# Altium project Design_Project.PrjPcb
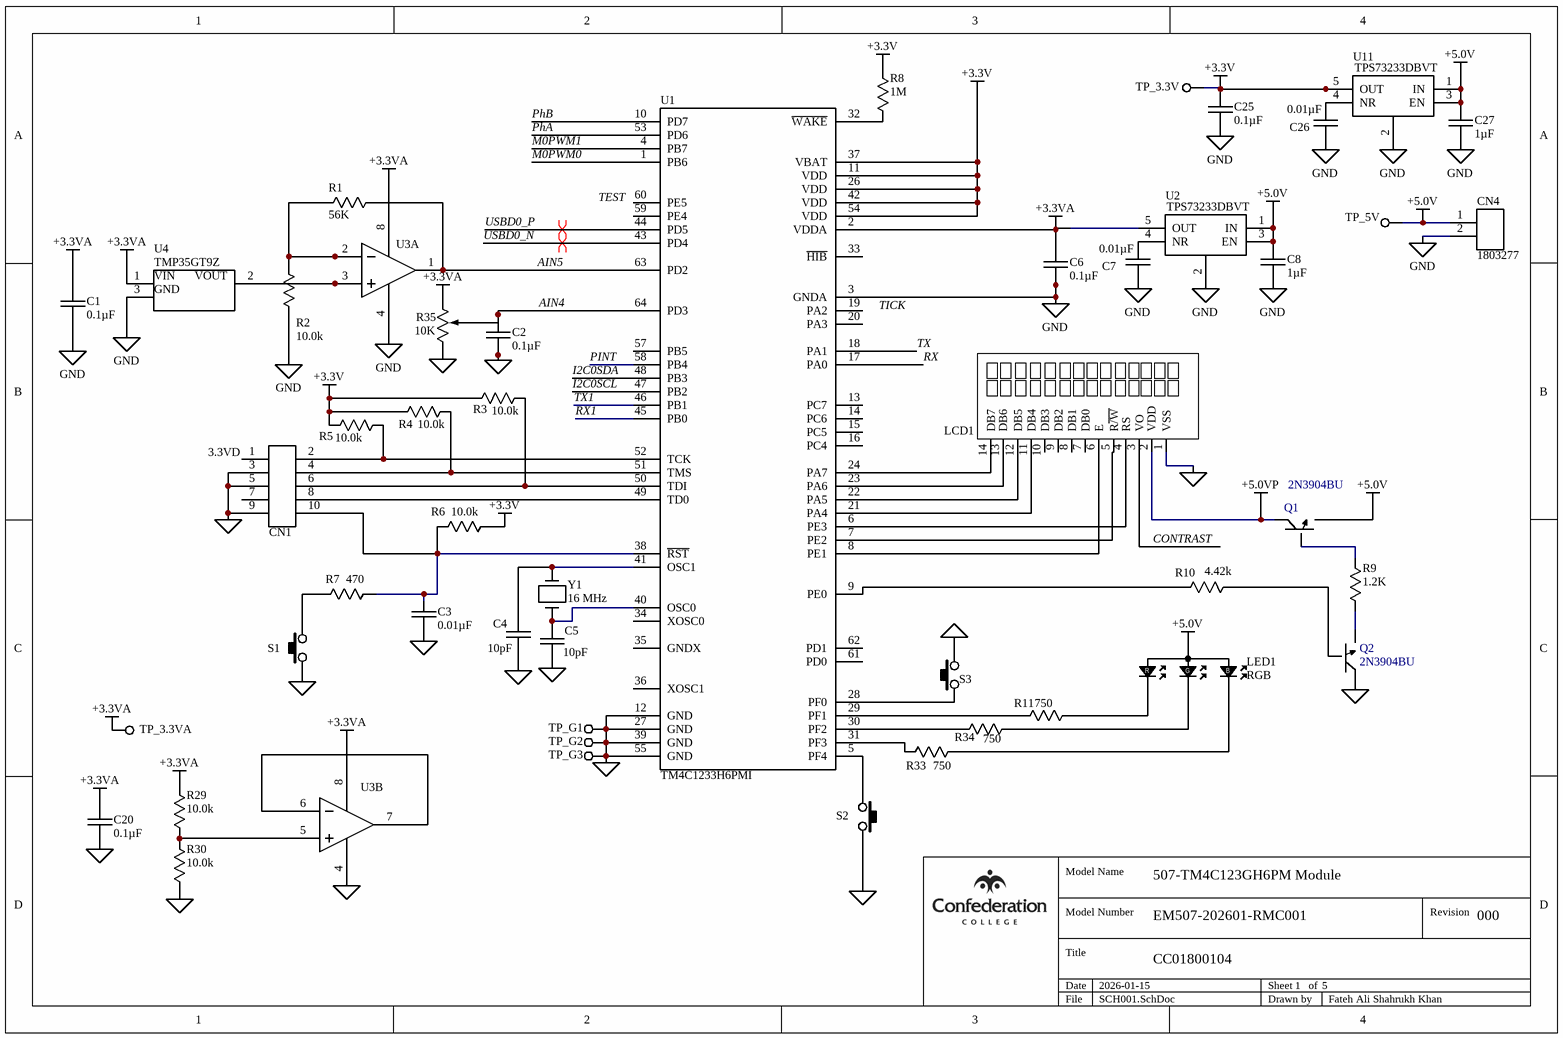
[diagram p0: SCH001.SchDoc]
3 sheets, 122 parts. Net scope: global (net labels, ports and power ports of the same name join across sheets).
Board file: PCB1.PcbDoc
Sheets:
  SCH001.SchDoc
  Sheet1.SchDoc
  Sheet2.SchDoc

## Sheet SCH001.SchDoc
size A4; SheetNumber: 1; SheetTotal: 3

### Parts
C1  0.1µF  [CAPC2012X14N]
C2  0.1µF  [CAPC2012X14N]
C3  0.01µF  [CAPC2012X08N]
C4  10pF  [CAPC2012X09N]
C5  10pF  [CAPC2012X09N]
C6  0.1µF  [CAPC2012X14N]
C7  0.01µF  [CAPC2012X08N]
C8  1µF  [CAPC2012X14N]
C20  0.1µF  [CAPC2012X14N]
C25  0.1µF  [CAPC2012X14N]
C26  0.01µF  [CAPC2012X08N]
C27  1µF  [CAPC2012X14N]
CN1  GRPB052VWVN-RC  [SULLINS_GRPB052VWVN-RC]  (value not drawn)
CN4  1803277  [PHOENIX_1803277]
LCD1  LCD MOD 32 DIG 16 X 2 REFLECTIVE  [LCM-S01602DTR/M]  (value not drawn)
LED1  RGB  [WURTH_150121M153000]
Q1  2N3904BU  [2N3904BU]
Q2  2N3904BU  [2N3904BU]
R1  56K  [th_res]
R2  10.0k  [RESC2012X06N]
R3  10.0k  [RESC2012X06N]
R4  10.0k  [RESC2012X06N]
R5  10.0k  [RESC2012X06N]
R6  10.0k  [RESC2012X06N]
R7  470  [th_res]
R8  1M  [th_res]
R9  1.2K  [RESC2012X06N]
R10  4.42k  [RESC2012X06N]
R11  750  [RESC2012X06N]
R29  10.0k  [RESC2012X06N]
R30  10.0k  [RESC2012X06N]
R33  750  [RESC2012X06N]
R34  750  [RESC2012X06N]
R35  10K  [PV36W103C01B00]
S1  KSC241JLFS  [CK_KSC241JLFS]  (value not drawn)
S2  KSC241JLFS  [CK_KSC241JLFS]  (value not drawn)
S3  KSC241JLFS  [CK_KSC241JLFS]  (value not drawn)
TP_3.3V  Test Point  [TP100]  (value not drawn)  (no BOM)
TP_3.3VA  Test Point  [TP100]  (value not drawn)  (no BOM)
TP_5V  Test Point  [TP100]  (value not drawn)  (no BOM)
TP_G1  Test Point  [TP100]  (value not drawn)  (no BOM)
TP_G2  Test Point  [TP100]  (value not drawn)  (no BOM)
TP_G3  Test Point  [TP100]  (value not drawn)  (no BOM)
U1  TM4C1233H6PMI  [TSQFP50P1200X1200X160-64N]
U2  TPS73233DBVT  [SOT95P280X145-5N]
U3  IC OPAMP GP 200KHZ RRO 8DIP  [LT1490CN8]  (value not drawn)  (parts A,B of 2)
U4  TMP35GT9Z  [TMP35GT9Z]
U11  TPS73233DBVT  [SOT95P280X145-5N]
Y1  16 MHz  [ABRACON_ABM3]

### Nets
+3.3V: C25.1 R3.1 R4.1 R5.2 R6.2 R8.2 TP_3.3V.1 U1.11(VDD) U1.26(VDD) U1.37(VBAT) U1.42(VDD) U1.54(VDD) U11.5(OUT)
+3.3VA: C1.1 C6.1 C20.1 R29.2 R35.2 TP_3.3VA.1 U1.2(VDDA) U2.5(OUT) U3.8(V+) U4.1
+5.0V: C8.1 C27.1 CN4.1 LED1.4(A) Q1.3 TP_5V.1 U2.1(IN) U2.3(EN) U11.1(IN) U11.3(EN)
+5.0VP: LCD1.2(VDD) Q1.1
GND: C1.2 C2.2 C3.2 C4.2 C5.2 C6.2 C7.2 C8.2 C20.2 C25.2 C26.2 C27.2 CN1.3 CN1.5 CN1.9 CN4.2 LCD1.1(VSS) Q2.1 R2.1 R30.1 R35.1 S1.1 S2.2 S3.2 TP_G1.1 TP_G2.1 TP_G3.1 U1.3(GNDA) U1.12(GND) U1.27(GND) U1.39(GND) U1.55(GND) U2.2(GND) U3.4(V-) U4.3 U11.2(GND)
AIN4: C2.1 R35.3 U1.64(PD3)
AIN5: R1.2 U1.63(PD2) U3.1
CONTRAST: LCD1.3(VO)
I2C0SCL: U1.47(PB2)
I2C0SDA: U1.48(PB3)
M0PWM0: U1.1(PB6)
M0PWM1: U1.4(PB7)
PhA: U1.53(PD6)
PhB: U1.10(PD7)
PINT: U1.58(PB4)
RX: U1.17(PA0)
RX1: U1.45(PB0)
TX: U1.18(PA1)
TX1: U1.46(PB1)
USBD0_N: U1.43(PD4)
USBD0_P: U1.44(PD5)
NetC3_1: C3.1 CN1.10 R6.1 R7.1 U1.38(~{RST})
NetC4_1: C4.1 U1.41(OSC1) Y1.2
NetC5_1: C5.1 U1.40(OSC0) Y1.1
NetC7_1: C7.1 U2.4(NR)
NetC26_1: C26.1 U11.4(NR)
NetCN1_2: CN1.2 R5.1 U1.52(TCK)
NetCN1_4: CN1.4 R4.2 U1.51(TMS)
NetCN1_6: CN1.6 R3.2 U1.50(TDI)
NetCN1_8: CN1.8 U1.49(TD0)
NetLCD1_4: LCD1.4(RS) U1.6(PE3)
NetLCD1_5: LCD1.5(R~{/W}) U1.7(PE2)
NetLCD1_6: LCD1.6(E) U1.8(PE1)
NetLCD1_11: LCD1.11(DB4) U1.21(PA4)
NetLCD1_12: LCD1.12(DB5) U1.22(PA5)
NetLCD1_13: LCD1.13(DB6) U1.23(PA6)
NetLCD1_14: LCD1.14(DB7) U1.24(PA7)
NetLED1_1: LED1.1(R) R11.2
NetLED1_2: LED1.2(G) R34.2
NetLED1_3: LED1.3(B) R33.2
NetQ1_2: Q1.2 R9.2
NetQ2_2: Q2.2 R10.2
NetQ2_3: Q2.3 R9.1
NetR1_1: R1.1 R2.2 U3.2(IN-)
NetR7_2: R7.2 S1.2
NetR8_1: R8.1 U1.32(~{WAKE})
NetR10_1: R10.1 U1.9(PE0)
NetR11_1: R11.1 U1.29(PF1)
NetR29_1: R29.1 R30.2 U3.5(IN+)
NetR33_1: R33.1 U1.31(PF3)
NetR34_1: R34.1 U1.30(PF2)
NetS2_1: S2.1 U1.5(PF4)
NetS3_1: S3.1 U1.28(PF0)
NetU3_3: U3.3(IN+) U4.2
NetU3_6: U3.6(IN-) U3.7

Not connected (* = marked no-connect by the designer): CN1 1 7; LCD1 7(DB0) 8(DB1) 9(DB2) 10(DB3); U1 13(PC7) 14(PC6) 15(PC5) 16(PC4) 19(PA2) 20(PA3) 33(~{HIB}) 34(XOSC0) 35(GNDX) 36(XOSC1) 57(PB5) 59(PE4) 60(PE5) 61(PD0) 62(PD1)

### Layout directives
differential pair: USBD0_N, USBD0_P

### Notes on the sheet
- (near U1) TEST
- (near U1) TICK
- (near CN1) 3.3VD

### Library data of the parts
C1 C2 C6 C20 C25 = UMK212B7104KGHT: 0.1µF/50V/±10% X7R Ceramic Chip Capacitor; Manufacturer: Taiyo Yuden
C3 C7 C26 = CL21B103KBANNNC: 0.01µF/50V/±10% X7R Ceramic Chip Capacitor; Manufacturer: Samsung Electro-Mechanics
C4 C5 = 08051A100KAT: 10pF/100V/±10% C0G (NP0) Ceramic Chip Capacitor; Manufacturer: Kyocera/AVX
C8 C27 = CL21B105KBFNNNG: 1µF/50V/±10% X7R Ceramic Chip Capacitor; Manufacturer: Samsung Electro-Mechanics
CN1 = GRPB052VWVN-RC: .050"[1.27mm] Contact Centers, Male Header; Manufacturer: Sullins Connector Solutions, Inc.
CN4 = 1803277: MC 1,5/2G-3,81 Pluggable Terminal Block 2 Pos 3.81mm pitch Through Hole Header; Manufacturer: Phoenix Contact
LCD1 = LCM-S01602DTR/M: Character Display Module Reflective 5 x 8 Dots TN - Twisted Nematic Without Backlight Parallel 66.00mm x 26.00mm x 6.50mm
LED1 = 150121M153000: Micro RGB SMD LED, Common Anode; Manufacturer: Wurth Elektronik
Q1 Q2 = 2N3904BU: Bipolar (BJT) Transistor NPN 40 V 200 mA 300MHz 625 mW Through Hole TO-92-3
R1 = CFR-25JR-52-56K: 56 kOhms ±5% 0.25W, 1/4W Through Hole Resistor Axial Automotive AEC-Q200 Carbon Film
R2-R6 R29 R30 = CR0805-FX-1002ELF: 10.0k, 1%, 0.125W Thick Film Chip Resistor; Manufacturer: Bourns
R7 = CRCW0603470RFKEAHP: 470 Ohms ±1% 0.333W, 1/3W Chip Resistor 0603 (1608 Metric) Automotive AEC-Q200, Pulse Withstanding Thick Film
R8 = CRCW06031M00FKEAHP: 1 MOhms ±1% 0.333W, 1/3W Chip Resistor 0603 (1608 Metric) Automotive AEC-Q200, Pulse Withstanding Thick Film
R9 = CR0805-FX-1201ELF: 1.2 kOhms ±1% 0.125W, 1/8W Chip Resistor 0805 (2012 Metric) Moisture Resistant Thick Film
R10 = CR0805-FX-4421ELF: 4.42k, 1%, 0.125W Thick Film Chip Resistor; Manufacturer: Bourns
R11 R33 R34 = CR0805-FX-7500ELF: 750, 1%, 0.125W Thick Film Chip Resistor; Manufacturer: Bourns
R35 = PV36W103C01B00: 10 kOhms 0.5W, 1/2W PC Pins Through Hole Trimmer Potentiometer Cermet 25 Turn Top Adjustment
S1-S3 = KSC241JLFS: KSC Series Sealed Tact Switch for SMT; Manufacturer: C&K Components
TP_3.3V TP_3.3VA TP_5V TP_G1-TP_G3 = TP3: Test Point, Surface Mount, 3 mm; Manufacturer: Confederation College
U1 = TM4C123GH6PM: Microcontroller; Manufacturer: Texas Instruments
U2 U11 = TPS73233DBVT: 250 mA, 3.3V Low Dropout Voltage Regulator; Manufacturer: Texas Instruments
U3 = LT1490CN8: Standard (General Purpose) Amplifier 2 Circuit Rail-to-Rail 8-PDIP
U4 = 505-TMP35GT9Z-ND: Temperature Sensor Analog, Local 10°C ~ 125°C 10mV/°C TO-92-3
Y1 = ABM3-16.000MHZ-B2-T: 16 MHz Miniature Ceramic SMD Crystal; Manufacturer: Abracon Corporation

## Sheet Sheet1.SchDoc
size 381 x 241 mm; SheetNumber: 2; SheetTotal: 3
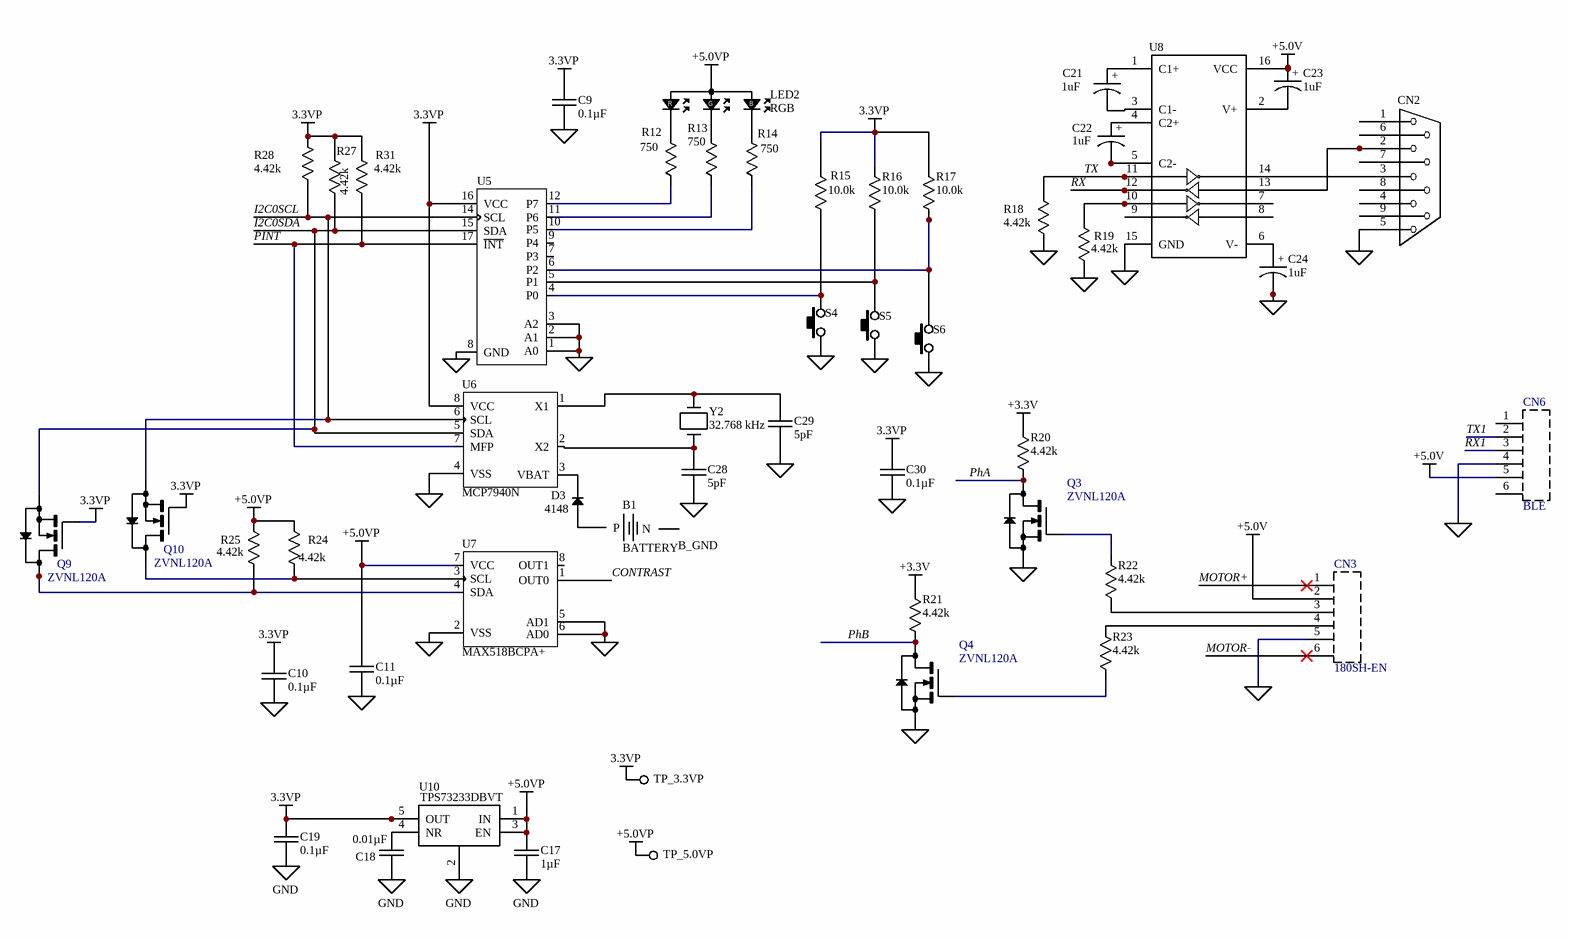
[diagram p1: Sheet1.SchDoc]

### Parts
B1  BATTERY  [BAT]
C9  0.1µF  [CAPC2012X14N]
C10  0.1µF  [CAPC2012X14N]
C11  0.1µF  [CAPC2012X14N]
C17  1µF  [CAPC2012X14N]
C18  0.01µF  [CAPC2012X08N]
C19  0.1µF  [CAPC2012X14N]
C21  1uF  [TAP105M035SCS]
C22  1uF  [TAP105M035SCS]
C23  1uF  [TAP105M035SCS]
C24  1uF  [TAP105M035SCS]
C28  5pF  [RCE5C1H5R0C0M1H03A]
C29  5pF  [RCE5C1H5R0C0M1H03A]
C30  0.1µF  [CAPC2012X14N]
CN2  CONN D-SUB PLUG 9POS PNL MNT  [DEP9]  (value not drawn)
CN3  180SH-EN  [6_PIN_MALE]
CN6  BLE  [6_PIN_MALE]
D3  4148  [1N4148]
LED2  RGB  [WURTH_150121M153000]
Q3  ZVNL120A  [ZVNL120A]
Q4  ZVNL120A  [ZVNL120A]
Q9  ZVNL120A  [ZVNL120A]
Q10  ZVNL120A  [ZVNL120A]
R12  750  [RESC2012X06N]
R13  750  [RESC2012X06N]
R14  750  [RESC2012X06N]
R15  10.0k  [RESC2012X06N]
R16  10.0k  [RESC2012X06N]
R17  10.0k  [RESC2012X06N]
R18  4.42k  [RESC2012X06N]
R19  4.42k  [RESC2012X06N]
R20  4.42k  [RESC2012X06N]
R21  4.42k  [RESC2012X06N]
R22  4.42k  [RESC2012X06N]
R23  4.42k  [RESC2012X06N]
R24  4.42k  [RESC2012X06N]
R25  4.42k  [RESC2012X06N]
R27  4.42k  [RESC2012X06N]
R28  4.42k  [RESC2012X06N]
R31  4.42k  [RESC2012X06N]
S4  KSC241JLFS  [CK_KSC241JLFS]  (value not drawn)
S5  KSC241JLFS  [CK_KSC241JLFS]  (value not drawn)
S6  KSC241JLFS  [CK_KSC241JLFS]  (value not drawn)
TP_3.3VP  Test Point  [TP100]  (value not drawn)  (no BOM)
TP_5.0VP  Test Point  [TP100]  (value not drawn)  (no BOM)
U5  IC XPNDR 100KHZ I2C 16SOIC  [PCF8574AN]  (value not drawn)
U6  MCP7940N  [MCP7940N-I/P]
U7  MAX518BCPA+  [LT1490CN8]
U8  IC DVR/RCVR DUAL-RS232 5V 16-DIP  [LT1081CN]  (value not drawn)
U10  TPS73233DBVT  [SOT95P280X145-5N]
Y2  32.768 kHz  [ABRACON_AB26TRB]

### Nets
3.3VP: C9.1 C10.1 C19.1 C30.1 Q9.2(G) Q10.2(G) R15.2 R16.2 R17.2 R27.2 R28.2 R31.2 TP_3.3VP.1 U5.16(VCC) U6.8(VCC) U10.5(OUT)
+3.3V: R20.2 R21.2
+5.0V: C23.1 CN3.2 CN6.5 U8.16(VCC)
+5.0VP: C11.1 C17.1 LED2.4(A) R24.2 R25.2 TP_5.0VP.1 U7.7(VCC) U10.1(IN) U10.3(EN)
GND: C9.2 C10.2 C11.2 C17.2 C18.2 C19.2 C24.2 C28.2 C29.2 C30.2 CN2.5 CN3.5 CN6.4 Q3.1(S) Q4.1(S) R18.1 R19.1 S4.1 S5.1 S6.1 U5.1(A0) U5.2(A1) U5.3(A2) U5.8(GND) U6.4(VSS) U7.2(VSS) U7.5(AD1) U7.6(AD0) U8.15(GND) U10.2(GND)
CONTRAST: U7.1(OUT0)
I2C0SCL: Q10.1(S) R28.1 U5.14(SCL) U6.6(SCL)
I2C0SDA: Q9.1(S) R27.1 U5.15(SDA) U6.5(SDA)
MOTOR+: CN3.1
MOTOR-: CN3.6
PhA: Q3.3(D) R20.1
PhB: Q4.3(D) R21.1
PINT: R31.1 U5.17(~{INT}) U6.7(MFP)
RX: U8.12(C2-)
RX1: CN6.3
TX: R18.2 U8.11(C2-)
TX1: CN6.2
NetB1_1: B1.1(P) D3.1(A)
NetC18_1: C18.1 U10.4(NR)
NetC21_1: C21.1 U8.1(C1+)
NetC21_2: C21.2 U8.3(C1-)
NetC22_1: C22.1 U8.4(C2+)
NetC22_2: C22.2 U8.5(C2-)
NetC23_2: C23.2 U8.2(V+)
NetC24_1: C24.1 U8.6(V-)
NetC28_1: C28.1 U6.2(X2) Y2.1
NetC29_1: C29.1 U6.1(X1) Y2.2
NetCN2_2: CN2.2 U8.13(C2-)
NetCN2_3: CN2.3 U8.14(C2-)
NetCN3_3: CN3.3 R22.1
NetCN3_4: CN3.4 R23.1
NetD3_2: D3.2(C) U6.3(VBAT)
NetLED2_1: LED2.1(R) R12.2
NetLED2_2: LED2.2(G) R13.2
NetLED2_3: LED2.3(B) R14.2
NetQ3_2: Q3.2(G) R22.2
NetQ4_2: Q4.2(G) R23.2
NetQ9_3: Q9.3(D) R25.1 U7.4(SDA)
NetQ10_3: Q10.3(D) R24.1 U7.3(SCL)
NetR12_1: R12.1 U5.12(P7)
NetR13_1: R13.1 U5.11(P6)
NetR14_1: R14.1 U5.10(P5)
NetR15_1: R15.1 S4.2 U5.4(P0)
NetR16_1: R16.1 S5.2 U5.5(P1)
NetR17_1: R17.1 S6.2 U5.6(P2)
NetR19_2: R19.2 U8.10(C2-)

Not connected (* = marked no-connect by the designer): B1 2(N); CN2 1 4(1) 6(1) 7(1) 8(1) 9(1); CN6 1 6(9); U5 7(P3) 9(P4); U7 8(OUT1); U8 7(C2-) 8(C2-) 9(C2-)

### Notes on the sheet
- (near B1) B_GND

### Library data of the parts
C9-C11 C19 C30 = UMK212B7104KGHT: as C1 on sheet SCH001
C17 = CL21B105KBFNNNG: as C8 on sheet SCH001
C18 = CL21B103KBANNNC: as C3 on sheet SCH001
C21-C24 = TAP105M035SCS: 1 µF Conformal Coated Tantalum Capacitors 35 V Radial 8Ohm
C28 C29 = RCE5C1H5R0C0M1H03A: 5 pF ±0.25pF 50V Ceramic Capacitor C0G, NP0 Radial
CN2 = ADDB9P: 9 Position D-Sub Plug, Male Pins Connector
CN6 = 180SH-EN
D3 = 1N4148: Diode 100 V 200mA Through Hole DO-35
LED2 = 150121M153000: as LED1 on sheet SCH001
Q3 Q4 Q9 Q10 = ZVNL120A: N-Channel 200 V 180mA (Ta) 700mW (Ta) Through Hole TO-92
R12-R14 = CR0805-FX-7500ELF: as R11 on sheet SCH001
R15-R17 = CR0805-FX-1002ELF: as R2 on sheet SCH001
R18-R25 R27 R28 R31 = CR0805-FX-4421ELF: as R10 on sheet SCH001
S4-S6 = KSC241JLFS: as S1 on sheet SCH001
TP_3.3VP TP_5.0VP = TP3: as TP_3.3V on sheet SCH001
U5 = PCF8574ADWR: I/O Expander 8 I2C 100 kHz 16-SOIC
U6 = MCP7940N: Real Time Clock (RTC) IC Clock/Calendar 64B I2C, 2-Wire Serial 8-SOIC (0.154", 3.90mm Width)
U8 = LT1081CN: 2/2 Transceiver Full RS232 16-PDIP
U10 = TPS73233DBVT: as U2 on sheet SCH001
Y2 = AB26TRB-32.768KHZ-T: 32.768 kHz Radial Can Crystal; Manufacturer: Abracon Corporation

## Sheet Sheet2.SchDoc
size A4; SheetNumber: 3; SheetTotal: 3
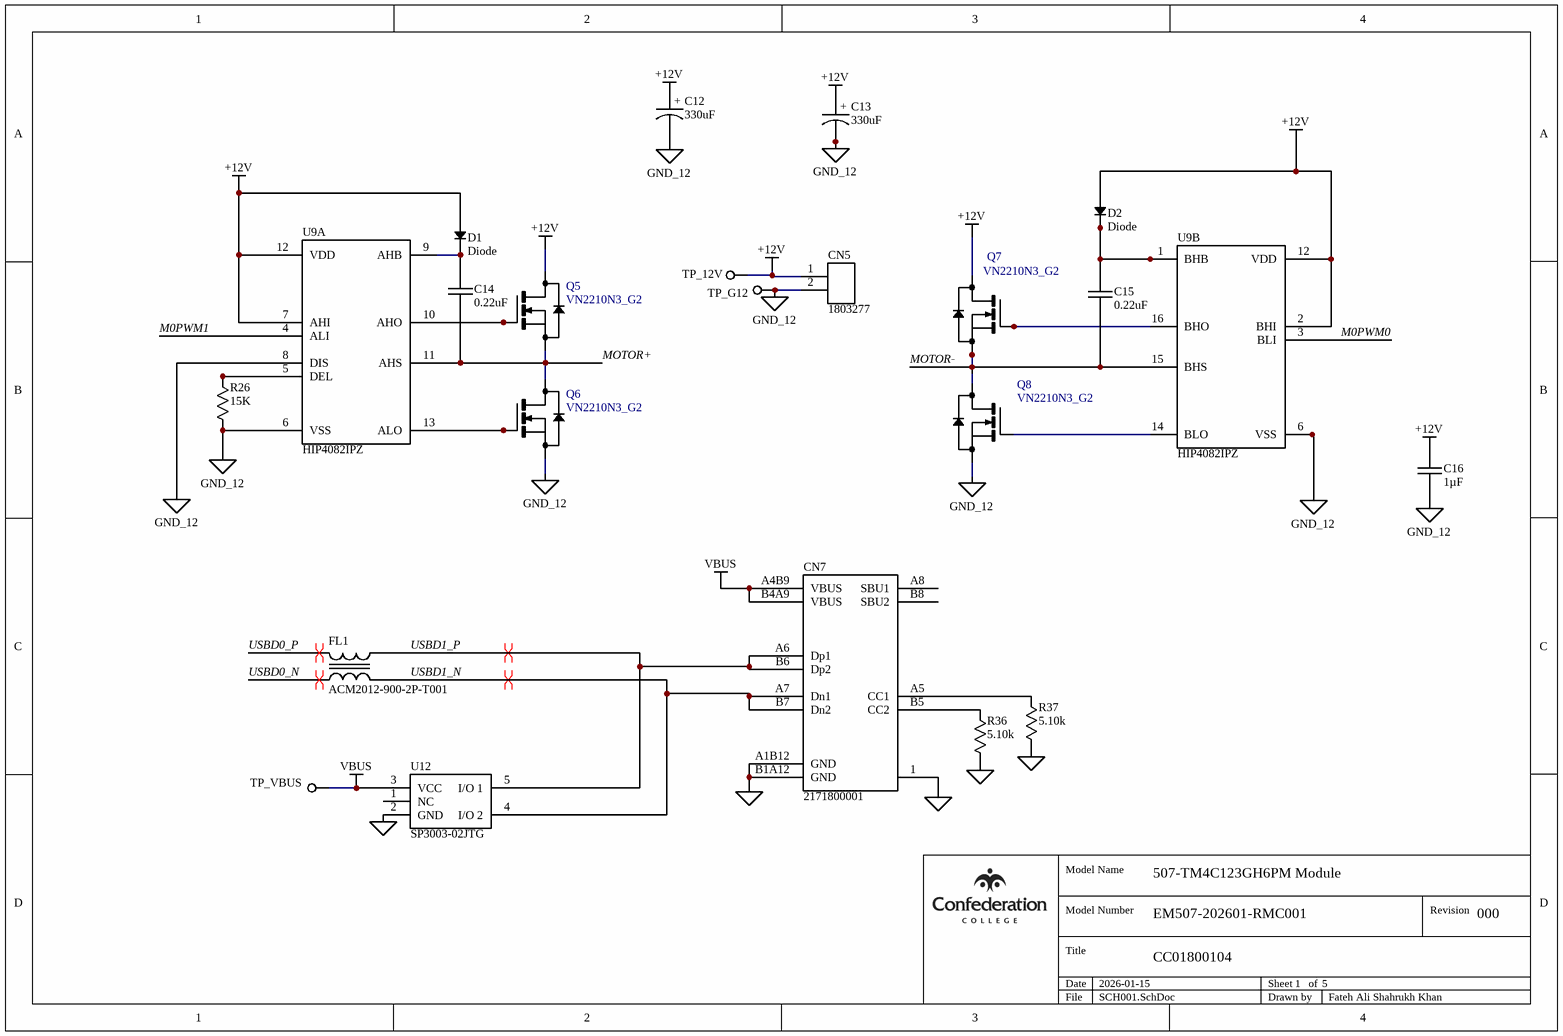
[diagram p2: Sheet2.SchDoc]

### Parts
C12  330uF  [PCAP_8x112_PAN]
C13  330uF  [PCAP_8x112_PAN]
C14  0.22uF  [C330C224K1R5TA]
C15  0.22uF  [C330C224K1R5TA]
C16  1µF  [CAPC2012X14N]
CN5  1803277  [PHOENIX_1803277]
CN7  2171800001  [MOLEX_2171800001]
D1  Diode  [UF4002]
D2  Diode  [UF4002]
FL1  ACM2012-900-2P-T001  [LITTELFUSE_ACM2012-900-2P-T001]
Q5  VN2210N3_G2
Q6  VN2210N3_G2
Q7  VN2210N3_G2
Q8  VN2210N3_G2
R26  15K  [th_res]
R36  5.10k  [RESC2012X06N]
R37  5.10k  [RESC2012X06N]
TP_12V  Test Point  [TP100]  (value not drawn)  (no BOM)
TP_G12  Test Point  [TP100]  (value not drawn)  (no BOM)
TP_VBUS  Test Point  [TP100]  (value not drawn)  (no BOM)
U9  HIP4082IPZ  [HIP4082IPZ]  (parts A,B of 2)
U12  SP3003-02JTG  [SOT65P220X110-5N]

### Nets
+12V: C12.1 C13.1 C16.1 CN5.1 D1.A(Anode) D2.A(Anode) Q5.3(D) Q7.3(D) TP_12V.1 U9.2(BHI) U9.7(AHI) U9.12(VDD)
GND: CN7.1(SHELL) CN7.A1B12(GND) CN7.B1A12(GND) R36.1 R37.1 U12.2(GND)
GND_12: C12.2 C13.2 C16.2 CN5.2 Q6.1(S) Q8.1(S) R26.1 TP_G12.1 U9.6(VSS) U9.8(DIS)
VBUS: CN7.A4B9(VBUS) CN7.B4A9(VBUS) TP_VBUS.1 U12.3(VCC)
M0PWM0: U9.3(BLI)
M0PWM1: U9.4(ALI)
MOTOR+: C14.2 Q5.1(S) Q6.3(D) U9.11(AHS)
MOTOR-: C15.2 Q7.1(S) Q8.3(D) U9.15(BHS)
USBD0_N: FL1.2
USBD0_P: FL1.1
USBD1_N: CN7.A7(Dn1) CN7.B7(Dn2) FL1.3 U12.4(I/O_2)
USBD1_P: CN7.A6(Dp1) CN7.B6(Dp2) FL1.4 U12.5(I/O_1)
NetC14_1: C14.1 D1.K(Cathode) U9.9(AHB)
NetC15_1: C15.1 D2.K(Cathode) U9.1(BHB)
NetCN7_A5: CN7.A5(CC1) R37.2
NetCN7_B5: CN7.B5(CC2) R36.2
NetQ5_2: Q5.2(G) U9.10(AHO)
NetQ6_2: Q6.2(G) U9.13(ALO)
NetQ7_2: Q7.2(G) U9.16(BHO)
NetQ8_2: Q8.2(G) U9.14(BLO)
NetR26_2: R26.2 U9.5(DEL)

Not connected (* = marked no-connect by the designer): CN7 A8(SBU1) B8(SBU2); U12 1(NC)

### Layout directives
differential pair: USBD0_N, USBD0_P, USBD1_N, USBD1_P

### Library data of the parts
C12 C13 = P5154-ND: 330 µF 25 V Aluminum Electrolytic Capacitors Radial, Can 2000 Hrs @ 85°C
C14 C15 = C330C224K1R5TA: 0.22 µF ±10% 100V Ceramic Capacitor X7R Radial
C16 = CL21B105KBFNNNG: as C8 on sheet SCH001
CN5 = 1803277: as CN4 on sheet SCH001
CN7 = 2171800001: USB-C Receptacle, Right-Angle, Surface Mount, Top Mount, Center Height 5.9mm, Single Row, 16 Circuits; Manufacturer: Molex
D1 D2 = UF4002: Diode 100 V 1A Through Hole DO-41
FL1 = ACM2012-900-2P-T001: Common Mode Filter; Manufacturer: TDK
R26 = CF1/4CT52R153J: 15 kOhms ±5% 0.25W, 1/4W Through Hole Resistor Axial Carbon Film
R36 R37 = CR0805-FX-5101ELF: 5.10k, 1%, 0.125W Thick Film Chip Resistor; Manufacturer: Bourns
TP_12V TP_G12 TP_VBUS = TP3: as TP_3.3V on sheet SCH001
U9 = HIP4082IBZ: Half Bridge, Full Bridge Driver DC Motors, General Purpose N-Channel MOSFET 16-SOIC
U12 = SP3003-02JTG: TVS Diode Array - Low Capacitance ESD Protection; Manufacturer: Littelfuse

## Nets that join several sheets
+3.3V: SCH001 (13 pins), Sheet1 (R20.2 R21.2)
+5.0V: SCH001 (10 pins), Sheet1 (C23.1 CN3.2 CN6.5 U8.16)
+5.0VP: SCH001 (LCD1.2 Q1.1), Sheet1 (9 pins)
GND: SCH001 (36 pins), Sheet1 (30 pins), Sheet2 (6 pins)
CONTRAST: SCH001 (LCD1.3), Sheet1 (U7.1)
I2C0SCL: SCH001 (U1.47), Sheet1 (Q10.1 R28.1 U5.14 U6.6)
I2C0SDA: SCH001 (U1.48), Sheet1 (Q9.1 R27.1 U5.15 U6.5)
M0PWM0: SCH001 (U1.1), Sheet2 (U9.3)
M0PWM1: SCH001 (U1.4), Sheet2 (U9.4)
MOTOR+: Sheet1 (CN3.1), Sheet2 (C14.2 Q5.1 Q6.3 U9.11)
MOTOR-: Sheet1 (CN3.6), Sheet2 (C15.2 Q7.1 Q8.3 U9.15)
PhA: SCH001 (U1.53), Sheet1 (Q3.3 R20.1)
PhB: SCH001 (U1.10), Sheet1 (Q4.3 R21.1)
PINT: SCH001 (U1.58), Sheet1 (R31.1 U5.17 U6.7)
RX: SCH001 (U1.17), Sheet1 (U8.12)
RX1: SCH001 (U1.45), Sheet1 (CN6.3)
TX: SCH001 (U1.18), Sheet1 (R18.2 U8.11)
TX1: SCH001 (U1.46), Sheet1 (CN6.2)
USBD0_N: SCH001 (U1.43), Sheet2 (FL1.2)
USBD0_P: SCH001 (U1.44), Sheet2 (FL1.1)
